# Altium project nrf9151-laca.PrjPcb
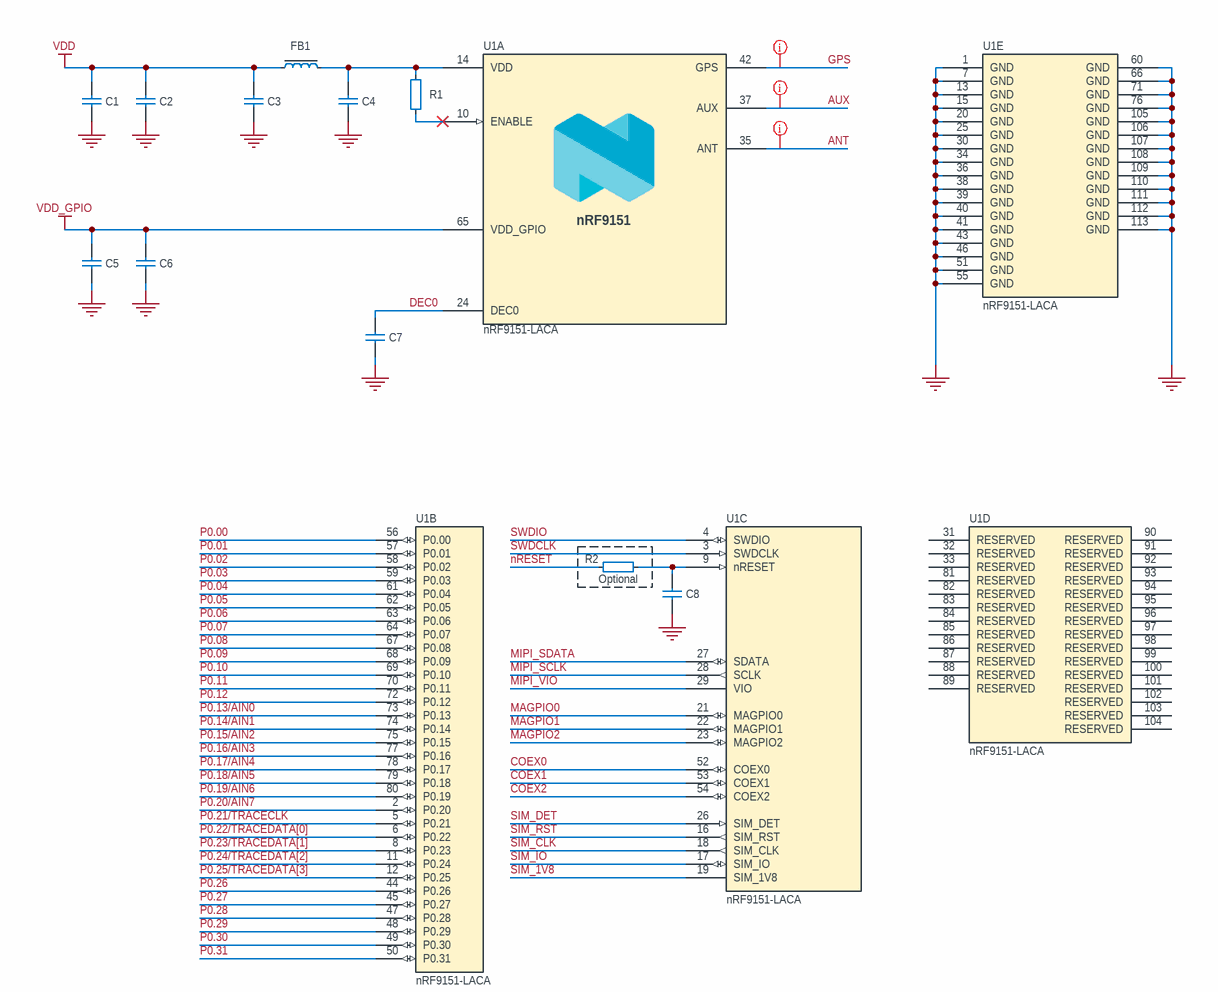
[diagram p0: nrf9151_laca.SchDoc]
1 sheet, 12 parts. Net scope: global (net labels, ports and power ports of the same name join across sheets).
Board file: nrf9151_laca.PcbDoc

## Sheet nrf9151_laca.SchDoc
size A3; Organization: Nordic Semiconductor; DocumentNumber: 1; Revision: 0.1; SheetNumber: 1; SheetTotal: 1; DrawnBy: KOD1; DocumentSize: A3; RefLayoutTitle: nRF9151-LACA Reference Layout; Device: nRF9151-LACA; Classification: CONFIDENTIAL

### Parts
C1  1.0µF  [CAPC0603X03L_C]  (value not drawn)
C2  1.0µF  [CAPC0603X03L_C]  (value not drawn)
C3  10µF  [CAPC1608X06L]  (value not drawn)
C4  10µF  [CAPC1608X06L]  (value not drawn)
C5  100nF  [CAPC0603X03L_C]  (value not drawn)
C6  4.7µF  [CAPC1005X04L]  (value not drawn)
C7  4.7µF  [CAPC1005X04L]  (value not drawn)
C8  100nF  [CAPC0603X03L_C]  (value not drawn)
FB1  22R@100M/6A  [INDC1608X06L]  (value not drawn)
R1  10k  [RESC0603X03L_C]  (value not drawn)
R2  Assembly: Optional  [RESC0603X03L_C]  (hidden comment: 1k)
U1  nRF9151-LACA  [LGA50P1210X1110X130-113N]  (parts A,B,C,D,E of 5)

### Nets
GND: C1.2 C2.2 C3.2 C4.2 C5.2 C6.2 C7.2 C8.2 U1.1(GND) U1.7(GND) U1.13(GND) U1.15(GND) U1.20(GND) U1.25(GND) U1.30(GND) U1.34(GND) U1.36(GND) U1.38(GND) U1.39(GND) U1.40(GND) U1.41(GND) U1.43(GND) U1.46(GND) U1.51(GND) U1.55(GND) U1.60(GND) U1.66(GND) U1.71(GND) U1.76(GND) U1.105(GND) U1.106(GND) U1.107(GND) U1.108(GND) U1.109(GND) U1.110(GND) U1.111(GND) U1.112(GND) U1.113(GND)
VDD: C1.1 C2.1 C3.1 FB1.1
VDD_GPIO: C5.1 C6.1 U1.65(VDD_GPIO)
ANT: U1.35(ANT)
AUX: U1.37(AUX)
COEX0: U1.52(COEX0)
COEX1: U1.53(COEX1)
COEX2: U1.54(COEX2)
DEC0: C7.1 U1.24(DEC0)
GPS: U1.42(GPS)
MAGPIO0: U1.21(MAGPIO0)
MAGPIO1: U1.22(MAGPIO1)
MAGPIO2: U1.23(MAGPIO2)
MIPI_SCLK: U1.28(SCLK)
MIPI_SDATA: U1.27(SDATA)
MIPI_VIO: U1.29(VIO)
nRESET: R2.1
P0.00: U1.56(P0.00)
P0.01: U1.57(P0.01)
P0.02: U1.58(P0.02)
P0.03: U1.59(P0.03)
P0.04: U1.61(P0.04)
P0.05: U1.62(P0.05)
P0.06: U1.63(P0.06)
P0.07: U1.64(P0.07)
P0.08: U1.67(P0.08)
P0.09: U1.68(P0.09)
P0.10: U1.69(P0.10)
P0.11: U1.70(P0.11)
P0.12: U1.72(P0.12)
P0.13/AIN0: U1.73(P0.13)
P0.14/AIN1: U1.74(P0.14)
P0.15/AIN2: U1.75(P0.15)
P0.16/AIN3: U1.77(P0.16)
P0.17/AIN4: U1.78(P0.17)
P0.18/AIN5: U1.79(P0.18)
P0.19/AIN6: U1.80(P0.19)
P0.20/AIN7: U1.2(P0.20)
P0.21/TRACECLK: U1.5(P0.21)
P0.22/TRACEDATA[0]: U1.6(P0.22)
P0.23/TRACEDATA[1]: U1.8(P0.23)
P0.24/TRACEDATA[2]: U1.11(P0.24)
P0.25/TRACEDATA[3]: U1.12(P0.25)
P0.26: U1.44(P0.26)
P0.27: U1.45(P0.27)
P0.28: U1.47(P0.28)
P0.29: U1.48(P0.29)
P0.30: U1.49(P0.30)
P0.31: U1.50(P0.31)
SIM_1V8: U1.19(SIM_1V8)
SIM_CLK: U1.18(SIM_CLK)
SIM_DET: U1.26(SIM_DET)
SIM_IO: U1.17(SIM_IO)
SIM_RST: U1.16(SIM_RST)
SWDCLK: U1.3(SWDCLK)
SWDIO: U1.4(SWDIO)
NetC4_1: C4.1 FB1.2 R1.1 U1.14(VDD)
NetC8_1: C8.1 R2.2 U1.9(nRESET)
NetR1_2: R1.2 U1.10(ENABLE)

Not connected (* = marked no-connect by the designer): U1 31(RESERVED) 32(RESERVED) 33(RESERVED) 81(RESERVED) 82(RESERVED) 83(RESERVED) 84(RESERVED) 85(RESERVED) 86(RESERVED) 87(RESERVED) 88(RESERVED) 89(RESERVED) 90(RESERVED) 91(RESERVED) 92(RESERVED) 93(RESERVED) 94(RESERVED) 95(RESERVED) 96(RESERVED) 97(RESERVED) 98(RESERVED) 99(RESERVED) 100(RESERVED) 101(RESERVED) 102(RESERVED) 103(RESERVED) 104(RESERVED)

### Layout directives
rule Impedance Constraint [Min = 50.00    Max = 50.00    ]; net class 50Ohm: ANT, AUX, GPS

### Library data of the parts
C1 C2 = C0201-1µ0-10V-X5R-GRM033R61A105ME15: Capacitor, X5R, ±20%, 10V; Manufacturer: Murata; Part number NEMS: 100200545; Artikkelnr Noca: N.A.; Pad Count: 2; Component Status: Active
C3 C4 = C0603-10µ-10V-X6S-GRM188C81A106MA73: Capacitor, Ceramic, 10µF 10V X6S 0603,±20%; Manufacturer: Murata; Part number NEMS: 100200520; Component Status: Active; Pad Count: 2; Artikkelnr Noca: N.A.
C5 = C0201-100n: Capacitor, X5R, ±10%; Manufacturer: N.A.; Part number IPS: 00000001248, 00000002505; Part number Norautron: 262071862; Part number NEMS: 100200078; Note: 16V; Pad Count: 2; Component Status: Active
C6 C7 = C0402-4µ7-10V-X5R: Capacitor, X5R, 10V; Manufacturer: Murata; Manufacturer Part Number: GRM155R61A475MEAAD; Part number NEMS: 100200415; Artikkelnr Noca: N.A.; Pad Count: 2; Component Status: Active
C8 = C0201-100n: Capacitor, X5R, ±10%; Pad Count: 2
FB1 = FB0603-22R@100MHz-6000mA: Ferrite Bead, 22 Ohm @ 100MHz, 6000mA, 8 mOhm Max; Manufacturer: Murata; Manufacturer Part Number: BLM18SD220SN1D; Component Status: Active; Pad Count: 2; Note: Chip EMIFIL Inductor Type Chip Ferrite Bead; Artikkelnr Noca: N.A.
R1 = R0201-10k: Resistor, ±1%, 0.05W; Manufacturer: N.A.; Part number IPS: 00000001255; Part number Norautron: 26107101; Part number NEMS: 100100065; Note: Chip Res 1%; Pad Count: 2; Component Status: Active
R2 = R0201-1k0: Resistor, ±1%, 0.05W; Pad Count: 2
U1 = nRF9151-LACAA0A: Low power System-in-Package with integrated LTE-M/NB-IoT modem and GPS; Manufacturer: Nordic Semiconductor; Part number NEMS: 102000328; Pad Count: 113; Component Status: Active; Note: N.A.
